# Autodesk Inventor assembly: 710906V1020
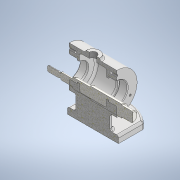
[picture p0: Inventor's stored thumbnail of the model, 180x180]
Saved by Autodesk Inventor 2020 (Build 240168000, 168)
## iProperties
Created: 2021-09
Part Number: 710906V1020
Document SubType Name: Assembly
Designer: Administrator
Author: Administrator
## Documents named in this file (3)
- C:\Users\Administrator\Desktop\710906V1020\710906V1020.iam
- C:\Users\Administrator\Desktop\710906V1020\본체.ipt
- C:\Users\Administrator\Desktop\710906V1020\축.ipt
